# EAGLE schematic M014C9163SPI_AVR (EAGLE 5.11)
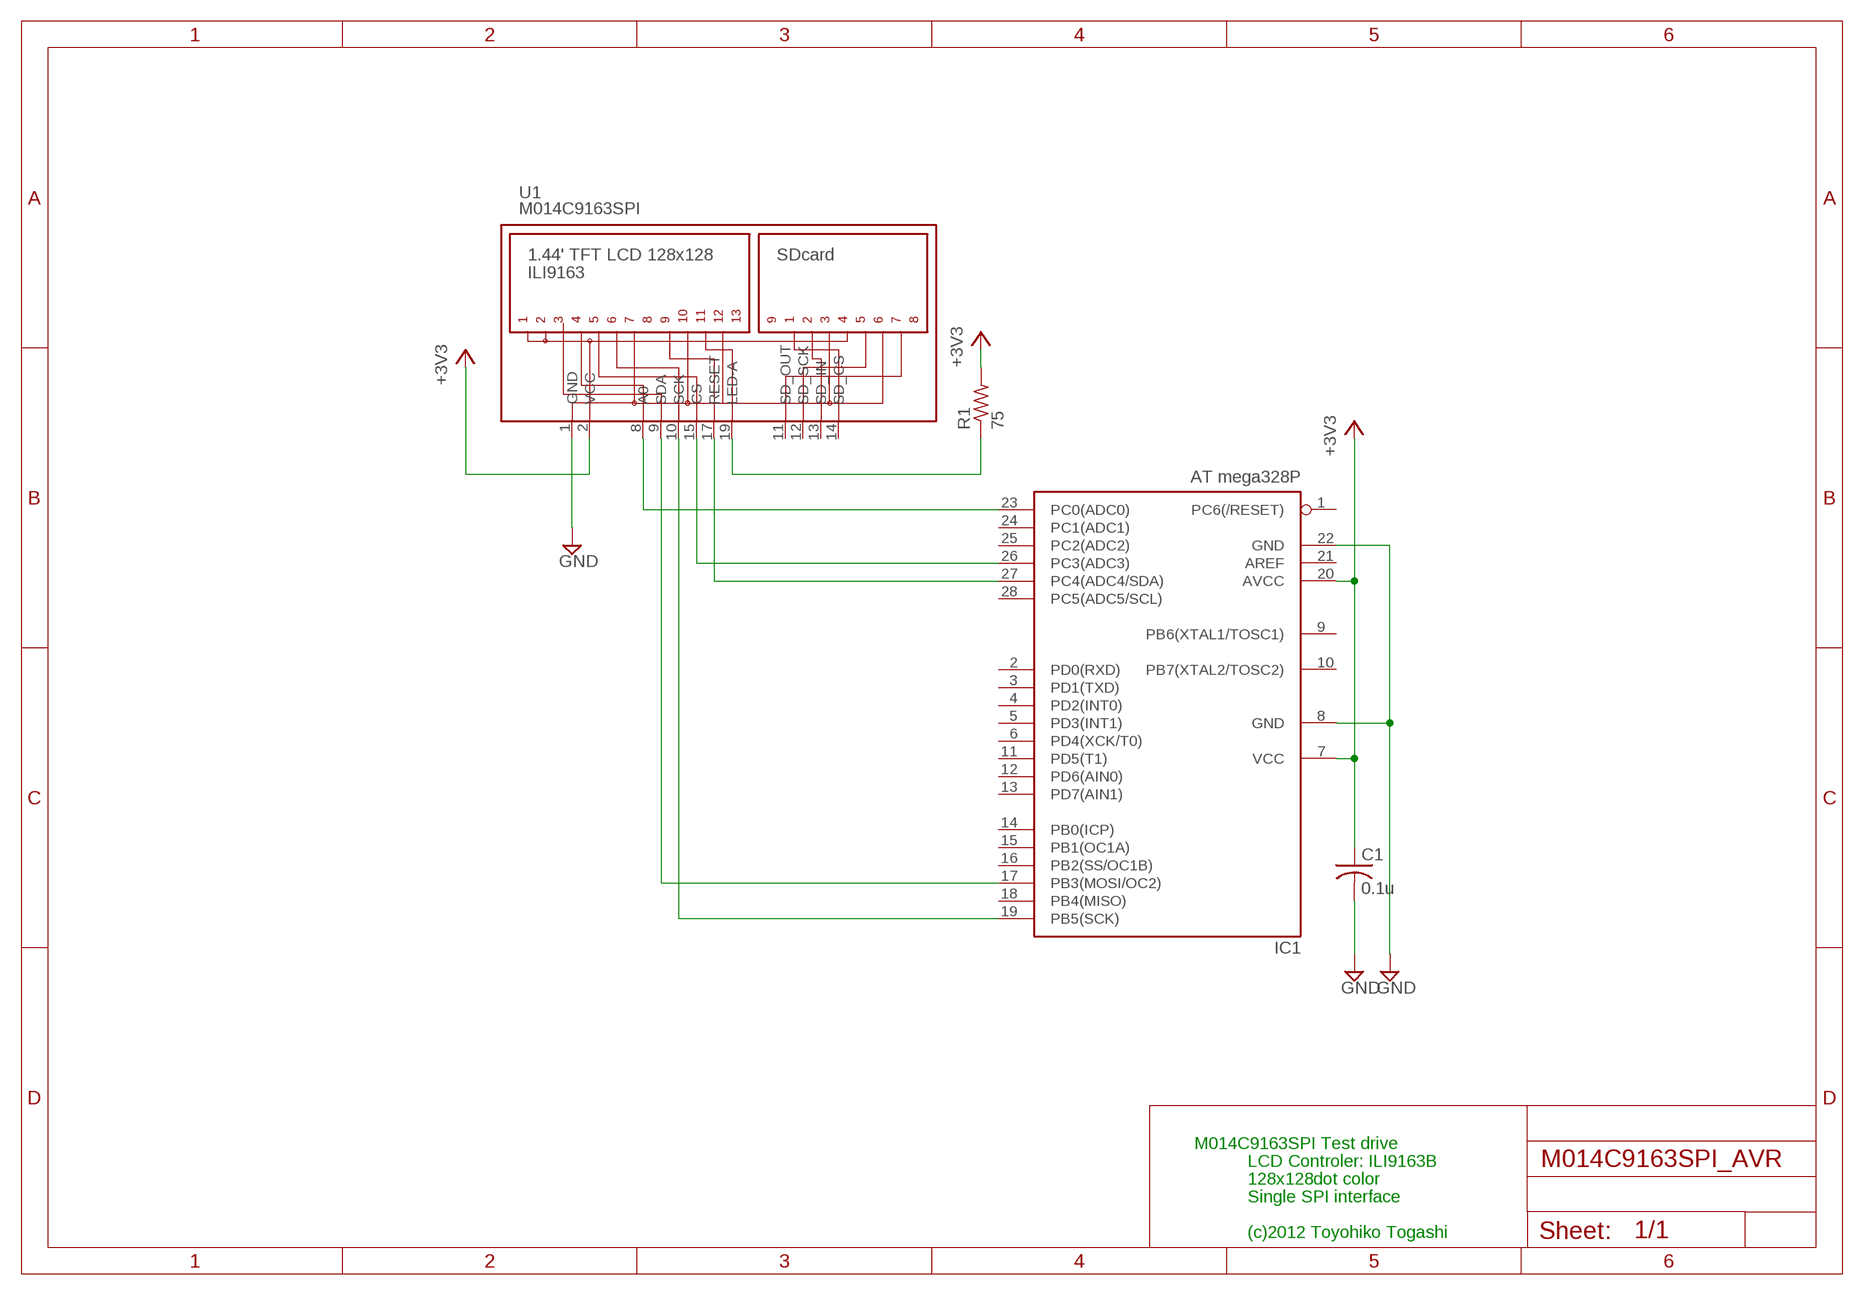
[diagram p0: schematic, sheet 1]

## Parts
C1  0.1u  C-US025-024X044  [C025-024X044]
IC1  AT mega328P  MEGA8-P  [DIL28-3]
R1  75  R-US_0204/5  [0204/5]
U1  M014C9163SPI  [M014C9163SPI]

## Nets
+3V3: C1.1 IC1.7(VCC) IC1.20(AVCC) R1.2 U1.2(VCC)
GND: C1.2 IC1.8(GND) IC1.22(GND) U1.1(GND)
N$1: IC1.23(PC0(ADC0)) U1.8(A0)
N$2: IC1.17(PB3(MOSI/OC2)) U1.9(SDA)
N$3: IC1.19(PB5(SCK)) U1.10(SCK)
N$4: IC1.26(PC3(ADC3)) U1.15(CS)
N$5: IC1.27(PC4(ADC4/SDA)) U1.17(RESET)
N$6: R1.1 U1.19(LED-A)
Unconnected: IC1.1(PC6(/RESET)) IC1.2(PD0(RXD)) IC1.3(PD1(TXD)) IC1.4(PD2(INT0)) IC1.5(PD3(INT1)) IC1.6(PD4(XCK/T0)) IC1.9(PB6(XTAL1/TOSC1)) IC1.10(PB7(XTAL2/TOSC2)) IC1.11(PD5(T1)) IC1.12(PD6(AIN0)) IC1.13(PD7(AIN1)) IC1.14(PB0(ICP)) IC1.15(PB1(OC1A)) IC1.16(PB2(SS/OC1B)) IC1.18(PB4(MISO)) IC1.21(AREF) IC1.24(PC1(ADC1)) IC1.25(PC2(ADC2)) IC1.28(PC5(ADC5/SCL)) U1.11(SD_OUT) U1.12(SD_SCK) U1.13(SD_IN) U1.14(SD_CS)

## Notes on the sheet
- M014C9163SPI Test drive
- LCD Controler: ILI9163B
- 128x128dot color
- Single SPI interface
- (c)2012 Toyohiko Togashi

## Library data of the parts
C1 = rcl:C-US: CAPACITOR, American symbol
IC1 = atmel:MEGA8-P: MICROCONTROLLER 8 Kbytes FLASH, 1 kbytes SRAM, 512 bytes EEPROM, USART, 4-channel 10 bit ADC, 2-channel 8 bit ADC Pin compatible with Atmega48, ATMega88, ATMega168 Source: avr.lbr; OC_FARNELL: unknown; OC_NEWARK: unknown
R1 = rcl:R-US_: RESISTOR, American symbol
U1 = TOG:M014C9163SPI: itendo M014C9163SPI board 1.44' TFT LCD Module and SDcard socket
